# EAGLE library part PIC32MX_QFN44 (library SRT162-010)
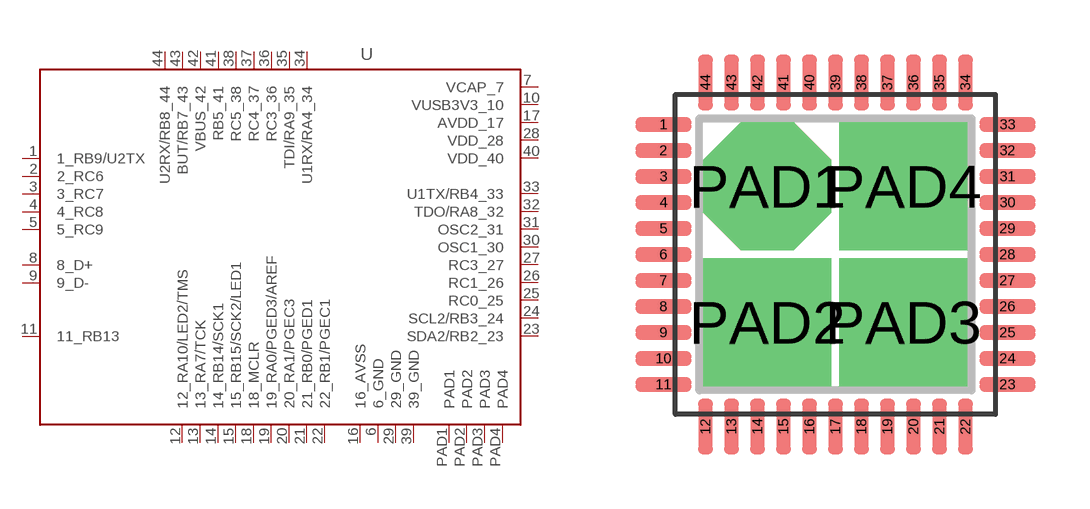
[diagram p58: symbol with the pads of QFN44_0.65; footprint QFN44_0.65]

Designator prefix U

## PIC32MX_QFN44  [QFN44_0.65]
1  1_RB9/U2TX  pas
2  2_RC6  pas
3  3_RC7  pas
4  4_RC8  pas
5  5_RC9  pas
6  6_GND  pwr
7  VCAP_7  sup
8  8_D+  pas
9  9_D-  pas
10  VUSB3V3_10  pas
11  11_RB13  pas
12  12_RA10/LED2/TMS  pas
13  13_RA7/TCK  pas
14  14_RB14/SCK1  pas
15  15_RB15/SCK2/LED1  pas
16  16_AVSS  pwr
17  AVDD_17  pwr
18  18_MCLR  pas
19  19_RA0/PGED3/AREF  pas
20  20_RA1/PGEC3  pas
21  21_RB0/PGED1  pas
22  22_RB1/PGEC1  pas
23  SDA2/RB2_23  pas
24  SCL2/RB3_24  pas
25  RC0_25  pas
26  RC1_26  pas
27  RC3_27  pas
28  VDD_28  pwr
29  29_GND  pwr
30  OSC1_30  pas
31  OSC2_31  pas
32  TDO/RA8_32  pas
33  U1TX/RB4_33  pas
34  U1RX/RA4_34  pas
35  TDI/RA9_35  pas
36  RC3_36  pas
37  RC4_37  pas
38  RC5_38  pas
39  39_GND  pwr
40  VDD_40  pwr
41  RB5_41  pas
42  VBUS_42  pas
43  BUT/RB7_43  pas
44  U2RX/RB8_44  pas
PAD1  PAD1  pas
PAD2  PAD2  pas
PAD3  PAD3  pas
PAD4  PAD4  pas

## Footprint QFN44_0.65 (pad centres in mm)
smd 1.4 x 0.37: 1 -4.3,3.25; 2 -4.3,2.6; 3 -4.3,1.95; 4 -4.3,1.3; 5 -4.3,0.65; 6 -4.3,0; 7 -4.3,-0.65; 8 -4.3,-1.3; 9 -4.3,-1.95; 10 -4.3,-2.6; 11 -4.3,-3.25; 23 4.3,-3.25; 24 4.3,-2.6; 25 4.3,-1.95; 26 4.3,-1.3; 27 4.3,-0.65; 28 4.3,0; 29 4.3,0.65; 30 4.3,1.3; 31 4.3,1.95; 32 4.3,2.6; 33 4.3,3.25
smd 0.37 x 1.4: 12 -3.25,-4.3; 13 -2.6,-4.3; 14 -1.95,-4.3; 15 -1.3,-4.3; 16 -0.65,-4.3; 17 0,-4.3; 18 0.65,-4.3; 19 1.3,-4.3; 20 1.95,-4.3; 21 2.6,-4.3; 22 3.25,-4.3; 34 3.25,4.3; 35 2.6,4.3; 36 1.95,4.3; 37 1.3,4.3; 38 0.65,4.3; 39 0,4.3; 40 -0.65,4.3; 41 -1.3,4.3; 42 -1.95,4.3; 43 -2.6,4.3; 44 -3.25,4.3
drill 0.6 pad 3.2 octagon: PAD1 -1.7,1.7
drill 0.6 pad 3.2 square: PAD2 -1.7,-1.7; PAD3 1.7,-1.7; PAD4 1.7,1.7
